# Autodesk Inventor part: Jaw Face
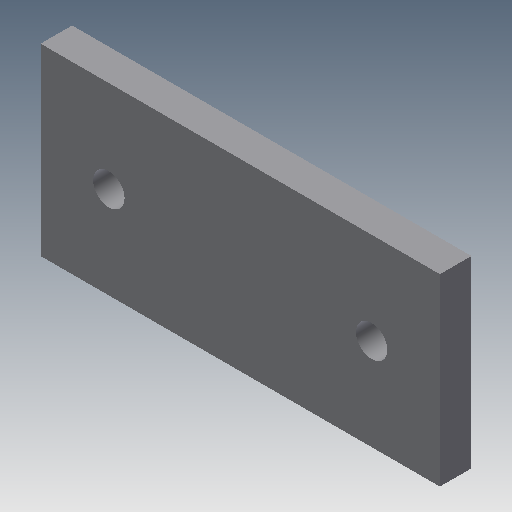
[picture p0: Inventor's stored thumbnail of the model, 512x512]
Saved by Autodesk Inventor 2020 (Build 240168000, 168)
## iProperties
Created: 2002-02
Part Number: Jaw Face
Document SubType Name: Modeling
Designer: ***
Density: 1 g/cm^3
Material: Generic
Appearance: Default
Control State: 0
Master: False
Checked Out: False
Shininess: 77.0
Length Units: 11269
Angle Units: 11279
Time Units: 11290
Mass Units: 11283
Length Display Precision: 3
Angle Display Precision: 2
Compacted: True
Density: 0.0
Volumn: 0.0
Area: 0.0
PropertySet Name: Model Information
Author: ***
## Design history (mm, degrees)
sketch "Sketch1"
  geometry: L1 (-79.661, -8.43)-(-3.661, -8.43); L2 (-3.661, -8.43)-(-3.661, -43.43); L3 (-3.661, -43.43)-(-79.661, -43.43); L4 (-79.661, -43.43)-(-79.661, -8.43); C1 r 3 at (-66.661, -25.93); C2 r 3 at (-16.661, -25.93)
  constraints: 8 end point, 2 centre point, 2 parallel, 1 equal radius, 1 horizontal, 1 perpendicular
  dimensions: "d0" = 76 distance of L2.end L3.end; "d1" = 6 diameter of C1; "d2" = 50 distance of C2.centre C1.centre; "d3" = 35 distance of L1.end L2.end; "d4" = 17.5 distance from line of L3 C2.centre; "d5" = 13 distance from line of L2 C2.centre; "d6" = 13 distance from line of L4 C1.centre
extrude "Extrusion1" new body sketch "Sketch1" stored distance "d7" = 6; taper "d8" = 0 deg
body "Solid1"
